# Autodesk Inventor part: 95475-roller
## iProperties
Author: Administrator
Shininess: 64.0
Angle Display Precision: 2
Document Length Units: 11272
Document Angle Units: 11286
Document Time Units: 11279
Document Mass Units: 11290
Document Length Units Precision: 3
Document Angle Units Precision: 2
Compacted: True
PropertySet Name: _Private Model Information
Created: 2002-04
Part Number: 95475-roller
Material: ASTM A36 HRS
Document SubType Name: Modeling
Designer: Administrator
Control State: 0
Master: False
Checked Out: False
PropertySet Name: Design Tracking Control
Density: 0.0
Volumn: 0.0
Area: 0.0
PropertySet Name: Model Information
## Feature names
1. Revolution1
